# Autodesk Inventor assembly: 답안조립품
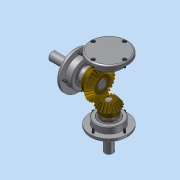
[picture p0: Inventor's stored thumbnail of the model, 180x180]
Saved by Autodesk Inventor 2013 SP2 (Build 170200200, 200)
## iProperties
Created: 2015-01
Part Number: 답안조립품
Document SubType Name: Assembly
Designer: dgall
Author: dgall
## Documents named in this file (15)
- C:\Documents and Settings\dgall\바탕 화면\450105V1019\답안조립품.iam
- C:\Documents and Settings\dgall\바탕 화면\450105V1019\본체.ipt
- C:\Documents and Settings\dgall\바탕 화면\450105V1019\커버.ipt
- C:\Documents and Settings\dgall\바탕 화면\450105V1019\커버2.ipt
- C:\Documents and Settings\dgall\바탕 화면\450105V1019\베어링 6203.ipt
- C:\Documents and Settings\dgall\바탕 화면\450105V1019\오일실.ipt
- C:\Documents and Settings\dgall\바탕 화면\450105V1019\서브 축.ipt
- 서브 축.ipt
- C:\Documents and Settings\dgall\바탕 화면\450105V1019\메인 축.ipt
- 메인 축.ipt
- C:\Documents and Settings\dgall\바탕 화면\450105V1019\서브 베벨기어.ipt
- C:\Documents and Settings\dgall\바탕 화면\450105V1019\메인 베벨기어.ipt
- C:\Documents and Settings\dgall\바탕 화면\450105V1019\키 5x5.ipt
- C:\Documents and Settings\dgall\바탕 화면\450105V1019\키 4x4.ipt
- C:\Documents and Settings\dgall\바탕 화면\450105V1019\M4.ipt
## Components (12 placed, 1 different names)
1. M4:1
2. M4:2
3. M4:3
4. M4:4
5. M4:5
6. M4:6
7. M4:7
8. M4:8
9. M4:9
10. M4:10
11. M4:11
12. M4:12
